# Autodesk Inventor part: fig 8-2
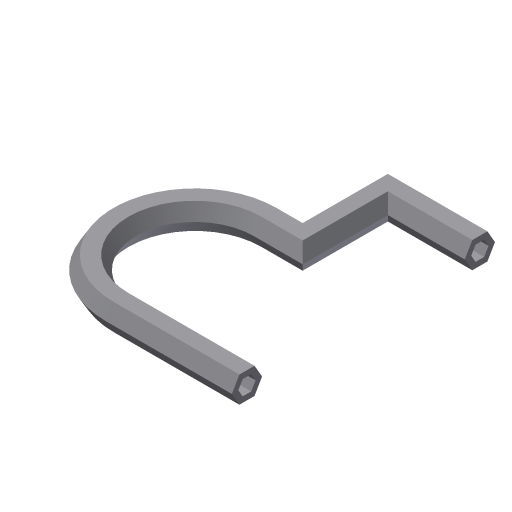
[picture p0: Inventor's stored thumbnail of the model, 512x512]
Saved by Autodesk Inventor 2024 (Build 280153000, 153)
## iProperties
Created: 2004-05
Part Number: fig 8-2
Document SubType Name: Modeling
Designer: CADCIM Technologies
Manufacturer: Standard
Standards Organization: Custom
Density: 1 g/cm^3
Material: Generic
Appearance: Default
Author: CADCIM Technologies
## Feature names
1. Sweep4
## Parameters: d3 = 0, d4 = 0
